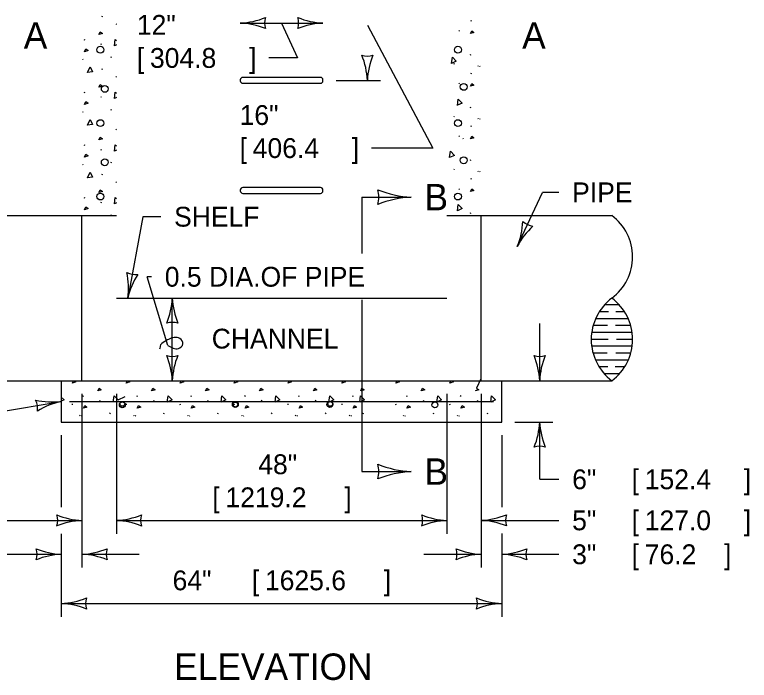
# Model space of a CAD drawing. Extents: x 49991.4 to 50028.3, y 49987.6 to 50011.4.
# Drawn here: x 50025.956 to 50028.18, y 49994.382 to 49996.396 of the extents above; entities that cross this region are included whole.
import ezdxf

# ---------------------------------------------------------------- set-up
doc = ezdxf.new("R2010")
doc.units = 0
for name, color, linetype in [('Level 1', 7, 'Continuous'), ('Level 2', 7, 'Continuous'), ('Level 3', 7, 'Continuous'), ('Level 4', 7, 'Continuous'), ('Level 6', 7, 'Continuous')]:
    doc.layers.add(name, color=color, linetype=linetype)

msp = doc.modelspace()

# ---------------------------------------------------------------- linework, layer by layer
at = {"layer": 'Level 1'}
for p, q in [((50026.2206, 49996.3905), (50026.222, 49996.3935)), ((50026.2622, 49996.3692), (50026.2635, 49996.3674)), ((50027.3379, 49996.3772), (50027.3392, 49996.3802)), ((50027.3006, 49996.3483), (50027.3019, 49996.3463)), ((50026.1667, 49996.3196), (50026.168, 49996.3226)), ((50026.2173, 49996.3059), (50026.2186, 49996.3089)), ((50027.3348, 49996.2766), (50027.3352, 49996.2736)), ((50026.161, 49996.2626), (50026.1624, 49996.2606)), ((50026.2476, 49996.2673), (50026.2489, 49996.2702)), ((50026.2206, 49996.231), (50026.222, 49996.234)), ((50027.286, 49996.2464), (50027.2873, 49996.2494)), ((50027.3576, 49996.2425), (50027.3589, 49996.2405)), ((50027.3626, 49996.2417), (50027.364, 49996.2397)), ((50026.2622, 49996.2097), (50026.2635, 49996.2079)), ((50027.3379, 49996.2178), (50027.3392, 49996.2208)), ((50026.6388, 49996.1992), (50026.6388, 49996.1965)), ((50026.8814, 49996.2066), (50026.6462, 49996.2066)), ((50026.6462, 49996.1891), (50026.8814, 49996.1891)), ((50026.8888, 49996.1965), (50026.8888, 49996.1992)), ((50027.3006, 49996.1888), (50027.3019, 49996.1868)), ((50026.1667, 49996.1601), (50026.168, 49996.1631)), ((50026.2173, 49996.1464), (50026.2186, 49996.1494)), ((50026.161, 49996.1032), (50026.1624, 49996.1012)), ((50026.2476, 49996.1078), (50026.2489, 49996.1108)), ((50027.3348, 49996.1172), (50027.3352, 49996.1142)), ((50027.286, 49996.0869), (50027.2873, 49996.0899)), ((50027.3576, 49996.083), (50027.3589, 49996.081)), ((50027.3626, 49996.0823), (50027.364, 49996.0803)), ((50027.3379, 49996.0584), (50027.3392, 49996.0614)), ((50026.2622, 49996.0502), (50026.2635, 49996.0484)), ((50027.3006, 49996.0294), (50027.3019, 49996.0274)), ((50027.3122, 49996.0228), (50027.3135, 49996.0208)), ((50026.1667, 49996.0006), (50026.168, 49996.0036)), ((50026.2173, 49995.987), (50026.2186, 49995.99)), ((50026.161, 49995.9437), (50026.1624, 49995.9417)), ((50026.2476, 49995.9484), (50026.2489, 49995.9514)), ((50027.3348, 49995.9578), (50027.3352, 49995.9548)), ((50027.286, 49995.9275), (50027.2873, 49995.9305)), ((50027.3576, 49995.9236), (50027.3589, 49995.9216)), ((50027.3626, 49995.9228), (50027.364, 49995.9208)), ((50026.2206, 49995.9121), (50026.222, 49995.9151)), ((50027.3379, 49995.8989), (50027.3392, 49995.9019)), ((50026.2622, 49995.8908), (50026.2635, 49995.889)), ((50026.6388, 49995.8658), (50026.6388, 49995.8632)), ((50026.8814, 49995.8733), (50026.6462, 49995.8733)), ((50026.6462, 49995.8558), (50026.8814, 49995.8558)), ((50026.8888, 49995.8632), (50026.8888, 49995.8658)), ((50027.3006, 49995.8699), (50027.3019, 49995.8679)), ((50026.1667, 49995.8412), (50026.168, 49995.8442)), ((50026.2173, 49995.8275), (50026.2186, 49995.8305)), ((50025.3647, 49995.7888), (50026.2635, 49995.7888)), ((50026.2476, 49995.7889), (50026.2489, 49995.7919)), ((50027.2641, 49995.7888), (50027.7638, 49995.7888)), ((50027.3348, 49995.7983), (50027.3352, 49995.7953)), ((50026.2635, 49995.5388), (50027.2641, 49995.5388)), ((50027.7536, 49995.4971), (50027.7254, 49995.4971)), ((50027.7865, 49995.518), (50027.7411, 49995.518)), ((50027.8022, 49995.4971), (50027.7761, 49995.4971)), ((50027.8132, 49995.4763), (50027.7143, 49995.4763)), ((50027.7504, 49995.4554), (50027.707, 49995.4554)), ((50027.8206, 49995.4554), (50027.775, 49995.4554)), ((50027.8249, 49995.4346), (50027.7027, 49995.4346)), ((50027.7526, 49995.4138), (50027.7013, 49995.4138)), ((50027.8263, 49995.4138), (50027.7772, 49995.4138)), ((50027.8249, 49995.393), (50027.7027, 49995.393)), ((50027.7494, 49995.3721), (50027.707, 49995.3721)), ((50027.8206, 49995.3721), (50027.7761, 49995.3721)), ((50027.8132, 49995.3513), (50027.7143, 49995.3513)), ((50027.7516, 49995.3304), (50027.7254, 49995.3304)), ((50027.8022, 49995.3304), (50027.774, 49995.3304)), ((50027.7865, 49995.3096), (50027.7411, 49995.3096)), ((50025.3647, 49995.2888), (50027.7638, 49995.2888)), ((50026.0968, 49995.2888), (50026.0968, 49995.1638)), ((50026.2598, 49995.2888), (50026.2599, 49995.2885)), ((50026.423, 49995.2888), (50026.4232, 49995.2885)), ((50026.5863, 49995.2888), (50026.5864, 49995.2885)), ((50026.7496, 49995.2888), (50026.7497, 49995.2885)), ((50026.9128, 49995.2888), (50026.913, 49995.2885)), ((50027.0059, 49995.2888), (50027.006, 49995.2885)), ((50027.2394, 49995.2888), (50027.2395, 49995.2885)), ((50027.4026, 49995.2888), (50027.4028, 49995.2885)), ((50027.4301, 49995.1638), (50027.4301, 49995.2888)), ((50026.163, 49995.2409), (50026.1644, 49995.2439)), ((50026.2136, 49995.2272), (50026.215, 49995.2302)), ((50026.3263, 49995.2409), (50026.3276, 49995.2439)), ((50026.3769, 49995.2272), (50026.3782, 49995.2302)), ((50026.4896, 49995.2409), (50026.4909, 49995.2439)), ((50026.5402, 49995.2272), (50026.5415, 49995.2302)), ((50026.6528, 49995.2409), (50026.6542, 49995.2439)), ((50026.7034, 49995.2272), (50026.7048, 49995.2302)), ((50026.8161, 49995.2409), (50026.8174, 49995.2439)), ((50026.8667, 49995.2272), (50026.868, 49995.2302)), ((50026.9794, 49995.2409), (50026.9807, 49995.2439)), ((50027.0098, 49995.2272), (50027.0111, 49995.2302)), ((50027.1426, 49995.2409), (50027.144, 49995.2439)), ((50027.1932, 49995.2272), (50027.1946, 49995.2302)), ((50027.3059, 49995.2409), (50027.3072, 49995.2439)), ((50027.3565, 49995.2272), (50027.3578, 49995.2302)), ((50026.1218, 49995.2263), (50027.4051, 49995.2263)), ((50026.1296, 49995.2189), (50026.1299, 49995.2159)), ((50026.2928, 49995.2189), (50026.2932, 49995.2159)), ((50026.4561, 49995.2189), (50026.4564, 49995.2159)), ((50026.6194, 49995.2189), (50026.6197, 49995.2159)), ((50026.7826, 49995.2189), (50026.783, 49995.2159)), ((50026.9459, 49995.2189), (50026.9462, 49995.2159)), ((50027.1091, 49995.2189), (50027.1095, 49995.2159)), ((50027.2724, 49995.2189), (50027.2727, 49995.2159)), ((50026.244, 49995.1886), (50026.2453, 49995.1916)), ((50026.4072, 49995.1886), (50026.4085, 49995.1916)), ((50026.5705, 49995.1886), (50026.5718, 49995.1916)), ((50026.7337, 49995.1886), (50026.7351, 49995.1916)), ((50026.897, 49995.1886), (50026.8983, 49995.1916)), ((50027.0103, 49995.1886), (50027.0116, 49995.1916)), ((50027.2235, 49995.1886), (50027.2249, 49995.1916)), ((50027.3868, 49995.1886), (50027.3881, 49995.1916)), ((50026.0968, 49995.1638), (50027.4301, 49995.1638)), ((50026.1523, 49995.1847), (50026.1536, 49995.1827)), ((50026.1574, 49995.184), (50026.1587, 49995.182)), ((50026.3155, 49995.1847), (50026.3169, 49995.1827)), ((50026.3206, 49995.184), (50026.322, 49995.182)), ((50026.4788, 49995.1847), (50026.4801, 49995.1827)), ((50026.4839, 49995.184), (50026.4852, 49995.182)), ((50026.6421, 49995.1847), (50026.6434, 49995.1827)), ((50026.6472, 49995.184), (50026.6485, 49995.182)), ((50026.8053, 49995.1847), (50026.8067, 49995.1827)), ((50026.8104, 49995.184), (50026.8118, 49995.182)), ((50026.9686, 49995.1847), (50026.9699, 49995.1827)), ((50026.9737, 49995.184), (50026.975, 49995.182)), ((50027.1319, 49995.1847), (50027.1332, 49995.1827)), ((50027.137, 49995.184), (50027.1383, 49995.182)), ((50027.2951, 49995.1847), (50027.2964, 49995.1827)), ((50027.3002, 49995.184), (50027.3016, 49995.182))]:
    msp.add_line(p, q, dxfattribs=at)
for points in [[(50026.2107, 49996.3367), (50026.2147, 49996.345), (50026.2214, 49996.34), (50026.2107, 49996.3367)], [(50027.3356, 49996.3396), (50027.3396, 49996.348), (50027.3462, 49996.343), (50027.3356, 49996.3396)], [(50026.2578, 49996.3024), (50026.2604, 49996.3215), (50026.2635, 49996.3184)], [(50026.2635, 49996.305), (50026.2581, 49996.3026)], [(50026.1674, 49996.2846), (50026.1714, 49996.2929), (50026.178, 49996.2879), (50026.1674, 49996.2846)], [(50027.278, 49996.2491), (50027.2807, 49996.2681), (50027.2926, 49996.2558), (50027.2784, 49996.2492)], [(50026.1757, 49996.222), (50026.1847, 49996.239), (50026.1916, 49996.2234), (50026.176, 49996.222)], [(50027.3356, 49996.1802), (50027.3396, 49996.1885), (50027.3462, 49996.1835), (50027.3356, 49996.1802)], [(50026.2107, 49996.1772), (50026.2147, 49996.1856), (50026.2214, 49996.1806), (50026.2107, 49996.1772)], [(50026.2578, 49996.143), (50026.2604, 49996.162), (50026.2635, 49996.1589)], [(50026.2635, 49996.1456), (50026.2581, 49996.1431)], [(50026.1674, 49996.1251), (50026.1714, 49996.1334), (50026.178, 49996.1284), (50026.1674, 49996.1251)], [(50027.2962, 49996.1221), (50027.2988, 49996.1412), (50027.3107, 49996.1288), (50027.2965, 49996.1222)], [(50026.1757, 49996.0626), (50026.1847, 49996.0796), (50026.1916, 49996.0639), (50026.176, 49996.0626)], [(50026.2107, 49996.0178), (50026.2147, 49996.0261), (50026.2214, 49996.0211), (50026.2107, 49996.0178)], [(50027.3356, 49996.0207), (50027.3396, 49996.029), (50027.3462, 49996.024), (50027.3356, 49996.0207)], [(50026.2578, 49995.9835), (50026.2604, 49996.0026), (50026.2635, 49995.9994)], [(50026.2635, 49995.9861), (50026.2581, 49995.9836)], [(50026.1674, 49995.9657), (50026.1714, 49995.974), (50026.178, 49995.969), (50026.1674, 49995.9657)], [(50027.2722, 49995.9641), (50027.2749, 49995.9832), (50027.2868, 49995.9708), (50027.2726, 49995.9642)], [(50026.1757, 49995.9031), (50026.1847, 49995.9201), (50026.1916, 49995.9044), (50026.176, 49995.9031)], [(50026.2107, 49995.8583), (50026.2147, 49995.8666), (50026.2214, 49995.8617), (50026.2107, 49995.8583)], [(50027.3356, 49995.8612), (50027.3396, 49995.8696), (50027.3462, 49995.8646), (50027.3356, 49995.8612)], [(50026.2578, 49995.8241), (50026.2604, 49995.8431), (50026.2635, 49995.84)], [(50026.1674, 49995.8062), (50026.1714, 49995.8146), (50026.178, 49995.8096), (50026.1674, 49995.8062)], [(50026.2635, 49995.8267), (50026.2581, 49995.8242)], [(50027.2962, 49995.8032), (50027.2988, 49995.8222), (50027.3107, 49995.8099), (50027.2965, 49995.8033)], [(50026.1303, 49995.2818), (50026.1336, 49995.2888)], [(50026.1362, 49995.2888), (50026.141, 49995.2852), (50026.1303, 49995.2818)], [(50026.2936, 49995.2818), (50026.2969, 49995.2888)], [(50026.2994, 49995.2888), (50026.3042, 49995.2852), (50026.2936, 49995.2818)], [(50026.4568, 49995.2818), (50026.4602, 49995.2888)], [(50026.4627, 49995.2888), (50026.4675, 49995.2852), (50026.4568, 49995.2818)], [(50026.6201, 49995.2818), (50026.6234, 49995.2888)], [(50026.626, 49995.2888), (50026.6308, 49995.2852), (50026.6201, 49995.2818)], [(50026.7834, 49995.2818), (50026.7867, 49995.2888)], [(50026.7892, 49995.2888), (50026.794, 49995.2852), (50026.7834, 49995.2818)], [(50026.9466, 49995.2818), (50026.95, 49995.2888)], [(50026.9525, 49995.2888), (50026.9573, 49995.2852), (50026.9466, 49995.2818)], [(50027.1099, 49995.2818), (50027.1132, 49995.2888)], [(50027.1158, 49995.2888), (50027.1206, 49995.2852), (50027.1099, 49995.2818)], [(50027.2732, 49995.2818), (50027.2765, 49995.2888)], [(50027.279, 49995.2888), (50027.2838, 49995.2852), (50027.2732, 49995.2818)], [(50027.3671, 49995.2941), (50027.3539, 49995.2664), (50027.3606, 49995.2614), (50027.3499, 49995.258)], [(50026.207, 49995.258), (50026.211, 49995.2664), (50026.2177, 49995.2614), (50026.207, 49995.258)], [(50026.3703, 49995.258), (50026.3743, 49995.2664), (50026.381, 49995.2614), (50026.3703, 49995.258)], [(50026.5336, 49995.258), (50026.5376, 49995.2664), (50026.5442, 49995.2614), (50026.5336, 49995.258)], [(50026.6968, 49995.258), (50026.7008, 49995.2664), (50026.7075, 49995.2614), (50026.6968, 49995.258)], [(50026.8601, 49995.258), (50026.8641, 49995.2664), (50026.8708, 49995.2614), (50026.8601, 49995.258)], [(50027.0032, 49995.258), (50027.0072, 49995.2664), (50027.0138, 49995.2614), (50027.0032, 49995.258)], [(50027.1866, 49995.258), (50027.1906, 49995.2664), (50027.1973, 49995.2614), (50027.1866, 49995.258)], [(50026.0968, 49995.2394), (50026.1054, 49995.2305), (50026.0968, 49995.2265)], [(50026.2542, 49995.2238), (50026.2568, 49995.2428), (50026.2687, 49995.2305), (50026.2907, 49995.2407)], [(50026.4174, 49995.2238), (50026.42, 49995.2428), (50026.432, 49995.2305), (50026.4177, 49995.2239)], [(50026.5807, 49995.2238), (50026.5833, 49995.2428), (50026.5952, 49995.2305), (50026.581, 49995.2239)], [(50026.744, 49995.2238), (50026.7466, 49995.2428), (50026.7585, 49995.2305), (50026.7442, 49995.2239)], [(50026.9072, 49995.2238), (50026.9098, 49995.2428), (50026.9218, 49995.2305), (50026.9075, 49995.2239)], [(50027.0003, 49995.2238), (50027.0029, 49995.2428), (50027.0148, 49995.2305), (50027.0006, 49995.2239)], [(50027.2338, 49995.2238), (50027.2364, 49995.2428), (50027.2483, 49995.2305), (50027.234, 49995.2239)], [(50027.397, 49995.2238), (50027.3996, 49995.2428), (50027.4116, 49995.2305), (50027.3973, 49995.2239)], [(50026.1637, 49995.2059), (50026.1677, 49995.2142), (50026.1744, 49995.2092), (50026.1637, 49995.2059)], [(50026.327, 49995.2059), (50026.331, 49995.2142), (50026.3376, 49995.2092), (50026.327, 49995.2059)], [(50026.4902, 49995.2059), (50026.4942, 49995.2142), (50026.5009, 49995.2092), (50026.4902, 49995.2059)], [(50026.6535, 49995.2059), (50026.6575, 49995.2142), (50026.6641, 49995.2092), (50026.6535, 49995.2059)], [(50026.8168, 49995.2059), (50026.8208, 49995.2142), (50026.8274, 49995.2092), (50026.8168, 49995.2059)], [(50026.98, 49995.2059), (50026.984, 49995.2142), (50026.9907, 49995.2092), (50026.98, 49995.2059)], [(50027.1433, 49995.2059), (50027.1473, 49995.2142), (50027.1539, 49995.2092), (50027.1433, 49995.2059)], [(50027.3066, 49995.2059), (50027.3106, 49995.2142), (50027.3172, 49995.2092), (50027.3066, 49995.2059)]]:
    msp.add_lwpolyline(points, dxfattribs=at)
for centre, radius in [((50026.2152, 49996.2906), 0.0104), ((50027.2978, 49996.2906), 0.0104), ((50027.3152, 49996.178), 0.0104), ((50026.2286, 49996.1721), 0.0104), ((50026.2152, 49996.0684), 0.0104), ((50027.2978, 49996.0684), 0.0104), ((50027.3152, 49995.9558), 0.0104), ((50026.2286, 49995.9499), 0.0104), ((50026.2152, 49995.8462), 0.0104), ((50027.2978, 49995.8462), 0.0104), ((50026.2815, 49995.2159), 0.00893), ((50026.2815, 49995.2187), 0.0074), ((50026.6236, 49995.2166), 0.00893), ((50026.6236, 49995.2166), 0.0074), ((50026.9101, 49995.2167), 0.00893), ((50026.9111, 49995.2187), 0.0074), ((50027.228, 49995.2157), 0.00893)]:
    msp.add_circle(centre, radius, dxfattribs=at)
for centre, radius, start, end in [((50026.6462, 49996.1992), 0.00742, 90, 180), ((50026.6462, 49996.1966), 0.00742, 180, 270), ((50026.8814, 49996.1992), 0.00742, 0, 90), ((50026.8814, 49996.1966), 0.00742, 270, 0), ((50026.6462, 49995.8659), 0.00742, 90, 180), ((50026.6462, 49995.8632), 0.00742, 180, 270), ((50026.8814, 49995.8659), 0.00742, 0, 90), ((50026.8814, 49995.8632), 0.00742, 270, 0), ((50027.67, 49995.6638), 0.1563, 306.8699, 53.1301), ((50027.8575, 49995.4138), 0.1563, 126.8699, 233.1301), ((50027.67, 49995.4138), 0.1563, 306.8699, 53.1301)]:
    msp.add_arc(centre, radius, start, end, dxfattribs=at)
at = {"layer": 'Level 3'}
for p, q in [((50026.6388, 49996.3712), (50026.8888, 49996.3712)), ((50026.9288, 49996.1978), (50027.0635, 49996.1978)), ((50027.4774, 49995.6948), (50027.5534, 49995.8588)), ((50027.6035, 49995.8588), (50027.5534, 49995.8588)), ((50026.3432, 49995.7851), (50026.2982, 49995.5388)), ((50026.3983, 49995.7851), (50026.3432, 49995.7851)), ((50026.3702, 49995.6034), (50026.3573, 49995.6034)), ((50026.4197, 49995.3953), (50026.3573, 49995.6034)), ((50026.4329, 49995.2888), (50026.4329, 49995.5388)), ((50027.5451, 49995.2888), (50027.5451, 49995.4622)), ((50026.1593, 49995.2488), (50026.1593, 49994.7235)), ((50026.2635, 49995.2488), (50026.2635, 49994.8259)), ((50027.2641, 49995.2488), (50027.2641, 49994.8259)), ((50027.3682, 49995.2488), (50027.3682, 49994.7235)), ((50025.0417, 49995.0471), (50026.0968, 49995.2263)), ((50027.4701, 49995.1638), (50027.5851, 49995.1638)), ((50027.5451, 49994.9904), (50027.5451, 49995.1638)), ((50026.0968, 49995.1238), (50026.0968, 49994.9059)), ((50027.4301, 49995.1238), (50027.4301, 49994.9062)), ((50027.5451, 49994.9904), (50027.6035, 49994.9904)), ((50025.9234, 49994.8659), (50026.1593, 49994.8659)), ((50026.2635, 49994.8659), (50027.2641, 49994.8659)), ((50027.3682, 49994.8662), (50027.6035, 49994.8662)), ((50026.0968, 49994.8259), (50026.0968, 49994.5746)), ((50027.4301, 49994.8262), (50027.4301, 49994.5746)), ((50025.9234, 49994.7635), (50026.0968, 49994.7635)), ((50026.1593, 49994.7635), (50026.3327, 49994.7635)), ((50027.1948, 49994.7635), (50027.3682, 49994.7635)), ((50027.4301, 49994.7635), (50027.6035, 49994.7635)), ((50026.0968, 49994.6146), (50027.4301, 49994.6146))]:
    msp.add_line(p, q, dxfattribs=at)
for points in [[(50026.7638, 49996.3712), (50026.8123, 49996.2656), (50026.7251, 49996.2656)], [(50027.0235, 49996.3645), (50027.2221, 49995.9928), (50027.0362, 49995.9928)]]:
    msp.add_lwpolyline(points, dxfattribs=at)
for centre, radius, start, end in [((50026.6273, 49996.6039), 0.233, 272.8273, 292.0772), ((50026.767, 49996.3712), 0.0548, 162.1388, 197.8612), ((50026.898, 49996.5934), 0.2223, 247.456, 267.6395), ((50026.7606, 49996.3712), 0.0548, 342.1388, 17.8612), ((50026.6297, 49996.1491), 0.2223, 67.456, 87.6395), ((50026.9003, 49996.1385), 0.233, 92.8273, 112.0772), ((50027.0235, 49996.326), 0.0548, 252.1388, 287.8612), ((50026.7908, 49996.1863), 0.233, 2.8273, 22.0772), ((50027.2456, 49996.1887), 0.2223, 157.456, 177.6395), ((50027.1686, 49996.1406), 0.2964, 247.456, 267.6395), ((50026.9855, 49995.8444), 0.073, 342.1388, 17.8612), ((50027.1717, 49995.5341), 0.3107, 92.8273, 112.0772), ((50027.2615, 49995.7822), 0.233, 337.969, 357.2189), ((50027.5313, 49995.8111), 0.0548, 227.2805, 263.0029), ((50027.6751, 49995.5931), 0.2223, 132.5977, 152.7812), ((50026.3213, 49995.665), 0.0548, 241.7849, 277.5072), ((50026.0672, 49995.5694), 0.233, 352.4733, 11.7232), ((50026.5151, 49995.4899), 0.2223, 147.102, 167.2856), ((50026.2108, 49995.548), 0.2223, 337.456, 357.6395), ((50026.6656, 49995.5503), 0.233, 182.8273, 202.0772), ((50026.4329, 49995.4106), 0.0548, 72.1388, 107.8612), ((50026.4329, 49995.417), 0.0548, 252.1388, 287.8612), ((50026.2002, 49995.2773), 0.233, 2.8273, 22.0772), ((50026.655, 49995.2797), 0.2223, 157.456, 177.6395), ((50027.5451, 49995.417), 0.0548, 252.1388, 287.8612), ((50027.3124, 49995.2773), 0.233, 2.8273, 22.0772), ((50027.7672, 49995.2797), 0.2223, 157.456, 177.6395), ((50026.0686, 49995.4469), 0.2223, 257.0955, 277.279), ((50025.9704, 49995.2049), 0.0548, 351.7783, 27.5007), ((50026.1471, 49994.9988), 0.233, 102.4668, 121.7167), ((50027.323, 49995.173), 0.2223, 337.456, 357.6395), ((50027.7778, 49995.1753), 0.233, 182.8273, 202.0772), ((50027.5451, 49995.0356), 0.0548, 72.1388, 107.8612), ((50027.1686, 49995.31), 0.2964, 247.456, 267.6395), ((50026.9855, 49995.0138), 0.073, 342.1388, 17.8612), ((50027.1717, 49994.7035), 0.3107, 92.8273, 112.0772), ((50026.1685, 49995.0881), 0.2223, 247.456, 267.6395), ((50026.0311, 49994.8659), 0.0548, 342.1388, 17.8612), ((50026.252, 49995.0986), 0.233, 272.8273, 292.0772), ((50026.3917, 49994.8659), 0.0548, 162.1388, 197.8612), ((50027.2733, 49995.0881), 0.2223, 247.456, 267.6395), ((50027.1359, 49994.8659), 0.0548, 342.1388, 17.8612), ((50027.3567, 49995.0989), 0.233, 272.8273, 292.0772), ((50027.4964, 49994.8662), 0.0548, 162.1388, 197.8612), ((50026.1708, 49994.6332), 0.233, 92.8273, 112.0772), ((50026.2544, 49994.6438), 0.2223, 67.456, 87.6395), ((50027.2756, 49994.6332), 0.233, 92.8273, 112.0772), ((50027.3591, 49994.6441), 0.2223, 67.456, 87.6395), ((50026.106, 49994.9857), 0.2223, 247.456, 267.6395), ((50025.9686, 49994.7635), 0.0548, 342.1388, 17.8612), ((50026.1083, 49994.5308), 0.233, 92.8273, 112.0772), ((50026.1478, 49994.9962), 0.233, 272.8273, 292.0772), ((50026.1502, 49994.5414), 0.2223, 67.456, 87.6395), ((50026.2875, 49994.7635), 0.0548, 162.1388, 197.8612), ((50027.24, 49994.7635), 0.0548, 342.1388, 17.8612), ((50027.3797, 49994.9962), 0.233, 247.9228, 267.1727), ((50027.3774, 49994.5414), 0.2223, 92.3605, 112.544), ((50027.421, 49994.9857), 0.2223, 272.3605, 292.544), ((50027.4186, 49994.5308), 0.233, 67.9228, 87.1727), ((50027.5583, 49994.7635), 0.0548, 162.1388, 197.8612), ((50026.0853, 49994.8473), 0.233, 272.8273, 292.0772), ((50026.225, 49994.6146), 0.0548, 162.1388, 197.8612), ((50027.4393, 49994.8367), 0.2223, 247.456, 267.6395), ((50027.3019, 49994.6146), 0.0548, 342.1388, 17.8612), ((50026.0877, 49994.3925), 0.2223, 67.456, 87.6395), ((50027.4416, 49994.3819), 0.233, 92.8273, 112.0772)]:
    msp.add_arc(centre, radius, start, end, dxfattribs=at)
msp.add_spline([(50026.4191, 49995.3955), (50026.4514, 49995.3866), (50026.4651, 49995.4003), (50026.4559, 49995.4163), (50026.4215, 49995.414), (50026.41, 49995.4072), (50026.3962, 49995.3934), (50026.3962, 49995.3911), (50026.3939, 49995.3843)], degree=3, dxfattribs=at)
at = {"layer": 'Level 4'}
for p, q in [((50026.1593, 49995.2888), (50026.1593, 49995.7888)), ((50027.3682, 49995.2888), (50027.3682, 49995.7888))]:
    msp.add_line(p, q, dxfattribs=at)
at = {"layer": 'Level 6'}
for p, q in [((50027.0064, 49995.8444), (50027.1564, 49995.8444)), ((50027.0064, 49995.8444), (50027.0064, 49995.6734)), ((50027.0064, 49995.5334), (50027.0064, 49995.0138)), ((50027.0064, 49995.0138), (50027.1564, 49995.0138))]:
    msp.add_line(p, q, dxfattribs=at)

# ---------------------------------------------------------------- texts
at = {"layer": 'Level 2'}
for s, height, p in [('12"', 0.06, (50026.3256, 49996.3356)), ('A', 0.0799, (50025.9832, 49996.2939)), ('A', 0.0799, (50027.4921, 49996.2939)), ('[', 0.06, (50026.3256, 49996.2356)), (']', 0.06, (50026.6653, 49996.2356)), ('304.8', 0.06, (50026.3653, 49996.2356)), ('16"', 0.06, (50026.6367, 49996.0628)), ('[', 0.06, (50026.6367, 49995.9628)), ('406.4', 0.06, (50026.6764, 49995.9628)), (']', 0.06, (50026.9764, 49995.9628)), ('B', 0.0799, (50027.1964, 49995.8044)), ('PIPE', 0.06, (50027.6435, 49995.8288)), ('SHELF', 0.06, (50026.4383, 49995.7551)), ('0.5 DIA.OF PIPE', 0.06, (50026.4102, 49995.5734)), ('CHANNEL', 0.06, (50026.5523, 49995.3861)), ('48"', 0.06, (50026.6932, 49995.0059)), ('B', 0.0799, (50027.1964, 49994.9739)), ('6" ', 0.06, (50027.6435, 49994.9604)), ('[', 0.06, (50027.8235, 49994.9604)), ('152.4', 0.06, (50027.8632, 49994.9604)), (']', 0.06, (50028.1632, 49994.9604)), ('[', 0.06, (50026.5541, 49994.9059)), ('1219.2', 0.06, (50026.5938, 49994.9059)), (']', 0.06, (50026.9538, 49994.9059)), ('[', 0.06, (50027.8235, 49994.8362)), ('127.0', 0.06, (50027.8632, 49994.8362)), (']', 0.06, (50028.1632, 49994.8362)), ('5" ', 0.06, (50027.6435, 49994.8362)), ('3" ', 0.06, (50027.6435, 49994.7335)), ('[', 0.06, (50027.8235, 49994.7335)), ('76.2', 0.06, (50027.8632, 49994.7335)), (']', 0.06, (50028.1032, 49994.7335)), ('64" ', 0.06, (50026.4337, 49994.6546)), ('[', 0.06, (50026.6737, 49994.6546)), ('1625.6', 0.06, (50026.7134, 49994.6546)), (']', 0.06, (50027.0734, 49994.6546)), ('ELEVATION', 0.08, (50026.4385, 49994.3833))]:
    msp.add_text(s, height=height, dxfattribs=at).set_placement(p)

doc.saveas('drawing.dxf')
